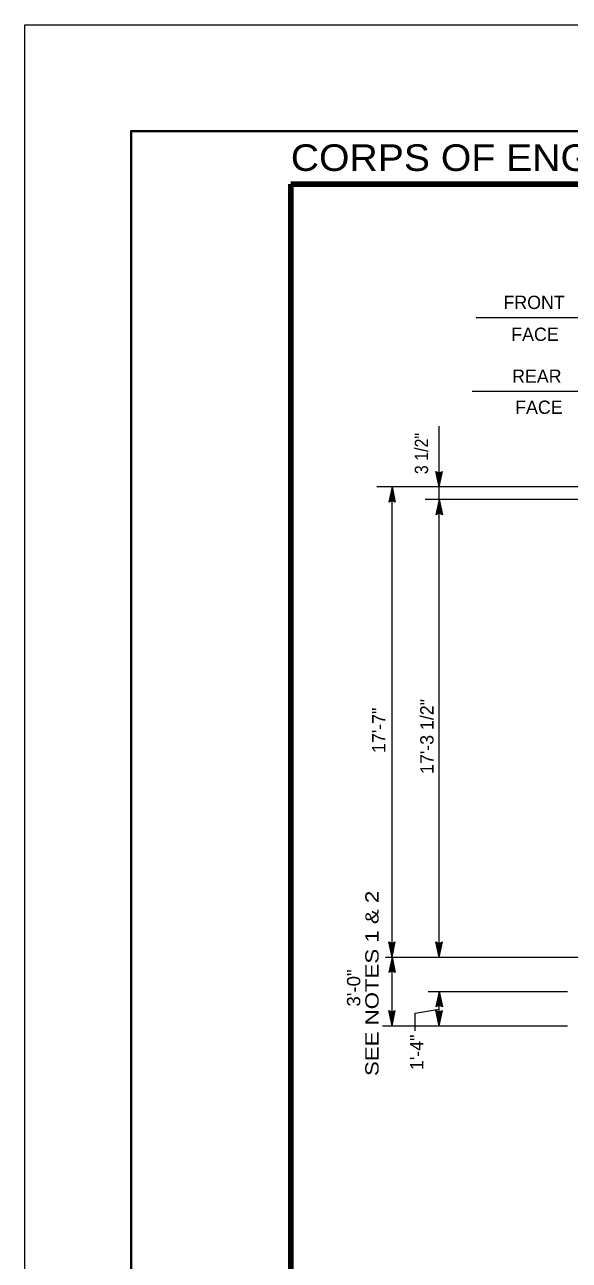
# Model space of a CAD drawing. Extents: x -22.3 to 19.7, y -11.8 to 18.2.
# Drawn here: x -22.31 to -17.19, y 6.54 to 18.16 of the extents above; entities that cross this region are included whole.
import ezdxf
from ezdxf.enums import TextEntityAlignment as Align

# ---------------------------------------------------------------- set-up
doc = ezdxf.new("R2010")
doc.units = 0
doc.header["$LTSCALE"] = 0.05
doc.layers.add('1', color=7, linetype='Continuous', lineweight=13)

msp = doc.modelspace()

# ---------------------------------------------------------------- linework, layer by layer
at = {"layer": '1'}
for p, q in [((-22.30942, -11.83969), (-22.30942, 18.16031)), ((-18.41442, 13.81631), (-18.44542, 13.96031)), ((-18.41442, 13.85331), (-18.43442, 13.94731)), ((-18.43442, 13.94731), (-18.41442, 13.93831)), ((-18.41442, 13.81631), (-18.38342, 13.96031)), ((-18.41442, 13.85331), (-18.39442, 13.94731)), ((-18.41442, 13.93831), (-18.39442, 13.94731)), ((-18.41442, 13.88931), (-18.42442, 13.93431)), ((-18.42442, 13.93431), (-18.41442, 13.93031)), ((-18.41442, 13.88931), (-18.40542, 13.93431)), ((-18.41442, 13.93031), (-18.40542, 13.93431)), ((-8.56742, 13.81631), (-19.00142, 13.81631)), ((-18.85842, 13.81631), (-18.88942, 13.67231)), ((-18.85842, 13.77931), (-18.87842, 13.68531)), ((-18.85842, 13.74331), (-18.86742, 13.69831)), ((-18.85842, 13.81631), (-18.82742, 13.67231)), ((-18.85842, 13.77931), (-18.83842, 13.68531)), ((-18.85842, 13.74331), (-18.84842, 13.69831)), ((-18.85842, 13.69431), (-18.87842, 13.68531)), ((-18.85842, 13.70231), (-18.86742, 13.69831)), ((-18.84842, 13.69831), (-18.85842, 13.70231)), ((-18.83842, 13.68531), (-18.85842, 13.69431)), ((-8.56742, 13.69631), (-18.54542, 13.69631)), ((-18.41442, 13.69631), (-18.44542, 13.55231)), ((-18.41442, 13.65931), (-18.43442, 13.56531)), ((-18.41442, 13.62331), (-18.42342, 13.57831)), ((-18.41442, 13.69631), (-18.38342, 13.55231)), ((-18.41442, 13.65931), (-18.39442, 13.56531)), ((-18.41442, 13.62331), (-18.40442, 13.57831)), ((-18.41442, 13.57431), (-18.43442, 13.56531)), ((-18.41442, 13.58231), (-18.42342, 13.57831)), ((-18.40442, 13.57831), (-18.41442, 13.58231)), ((-18.39442, 13.56531), (-18.41442, 13.57431)), ((-18.85842, 9.39231), (-18.88942, 9.53631)), ((-18.85842, 9.39231), (-18.82742, 9.53631)), ((-18.41442, 9.39231), (-18.44542, 9.53631)), ((-18.41442, 9.39231), (-18.38342, 9.53631)), ((-18.85842, 9.42931), (-18.87842, 9.52331)), ((-18.87842, 9.52331), (-18.85842, 9.51431)), ((-18.85842, 9.46531), (-18.86842, 9.51031)), ((-18.86842, 9.51031), (-18.85842, 9.50631)), ((-18.85842, 9.42931), (-18.83842, 9.52331)), ((-18.85842, 9.51431), (-18.83842, 9.52331)), ((-18.85842, 9.46531), (-18.84942, 9.51031)), ((-18.85842, 9.50631), (-18.84942, 9.51031)), ((-18.41442, 9.42931), (-18.43442, 9.52331)), ((-18.43442, 9.52331), (-18.41442, 9.51431)), ((-18.41442, 9.46531), (-18.42442, 9.51031)), ((-18.42442, 9.51031), (-18.41442, 9.50631)), ((-18.41442, 9.42931), (-18.39442, 9.52331)), ((-18.41442, 9.51431), (-18.39442, 9.52331)), ((-18.41442, 9.46531), (-18.40542, 9.51031)), ((-18.41442, 9.50631), (-18.40542, 9.51031)), ((-18.92042, 9.39231), (-15.40142, 9.39231)), ((-18.85842, 9.39231), (-18.88942, 9.24831)), ((-18.85842, 9.35531), (-18.87842, 9.26131)), ((-18.85842, 9.31931), (-18.86742, 9.27431)), ((-18.85842, 9.39231), (-18.82742, 9.24831)), ((-18.85842, 9.35531), (-18.83842, 9.26131)), ((-18.85842, 9.31931), (-18.84842, 9.27431)), ((-18.85842, 9.27031), (-18.87842, 9.26131)), ((-18.85842, 9.27831), (-18.86742, 9.27431)), ((-18.84842, 9.27431), (-18.85842, 9.27831)), ((-18.83842, 9.26131), (-18.85842, 9.27031)), ((-18.51842, 9.07131), (-17.21042, 9.07131)), ((-18.41442, 9.07131), (-18.44542, 8.92731)), ((-18.41442, 8.74831), (-18.41442, 9.07131)), ((-18.41442, 9.07131), (-18.38342, 8.92731)), ((-18.41442, 9.03431), (-18.43442, 8.94031)), ((-18.41442, 8.94931), (-18.43442, 8.94031)), ((-18.41442, 8.99831), (-18.42342, 8.95331)), ((-18.41442, 8.95731), (-18.42342, 8.95331)), ((-18.41442, 9.03431), (-18.39442, 8.94031)), ((-18.41442, 8.99831), (-18.40442, 8.95331)), ((-18.40442, 8.95331), (-18.41442, 8.95731)), ((-18.39442, 8.94031), (-18.41442, 8.94931)), ((-18.85842, 8.74831), (-18.88942, 8.89231)), ((-18.85842, 8.78531), (-18.87842, 8.87931)), ((-18.87842, 8.87931), (-18.85842, 8.87031)), ((-18.85842, 8.82131), (-18.86842, 8.86631)), ((-18.86842, 8.86631), (-18.85842, 8.86231)), ((-18.85842, 8.74831), (-18.82742, 8.89231)), ((-18.85842, 8.78531), (-18.83842, 8.87931)), ((-18.85842, 8.87031), (-18.83842, 8.87931)), ((-18.85842, 8.82131), (-18.84942, 8.86631)), ((-18.85842, 8.86231), (-18.84942, 8.86631)), ((-18.41442, 8.74831), (-18.44542, 8.89231)), ((-18.41442, 8.78531), (-18.43442, 8.87931)), ((-18.43442, 8.87931), (-18.41442, 8.87031)), ((-18.41442, 8.82131), (-18.42442, 8.86631)), ((-18.42442, 8.86631), (-18.41442, 8.86231)), ((-18.41442, 8.74831), (-18.38342, 8.89231)), ((-18.41442, 8.78531), (-18.39442, 8.87931)), ((-18.41442, 8.87031), (-18.39442, 8.87931)), ((-18.41442, 8.82131), (-18.40542, 8.86631)), ((-18.41442, 8.86231), (-18.40542, 8.86631)), ((-18.94642, 8.74831), (-17.21042, 8.74831))]:
    msp.add_line(p, q, dxfattribs=at)
for points in [[(-22.30942, 18.16031), (19.69058, 18.16031), (19.69058, -11.83969)], [(-18.06742, 15.40731), (-17.03142, 15.40731), (-16.93242, 15.40731), (-10.43842, 15.40731), (-10.30242, 15.40731), (-8.44242, 15.40731), (-8.32942, 15.40731), (-7.44542, 15.40731)], [(-18.10442, 14.71431), (-17.03142, 14.71431), (-16.93242, 14.71431), (-14.20242, 14.71431), (-13.95142, 14.71431), (-12.68842, 14.71431), (-12.43842, 14.71431), (-11.43942, 14.71431), (-11.31142, 14.71431), (-10.43842, 14.71431), (-10.30342, 14.71431), (-9.17242, 14.71431), (-9.07942, 14.71431), (-8.44242, 14.71431), (-8.33342, 14.71431), (-7.78542, 14.71431)], [(-18.41442, 9.39231), (-18.41442, 13.69631), (-18.41442, 13.81631), (-18.41442, 14.38631)], [(-18.44542, 13.96031), (-18.41442, 13.94631), (-18.38342, 13.96031)], [(-18.85842, 8.74831), (-18.85842, 9.39231), (-18.85842, 13.81631)], [(-18.82742, 13.67231), (-18.85842, 13.68631), (-18.88942, 13.67231)], [(-18.38342, 13.55231), (-18.41442, 13.56631), (-18.44542, 13.55231)], [(-18.88942, 9.53631), (-18.85842, 9.52231), (-18.82742, 9.53631)], [(-18.44542, 9.53631), (-18.41442, 9.52231), (-18.38342, 9.53631)], [(-18.82742, 9.24831), (-18.85842, 9.26231), (-18.88942, 9.24831)], [(-18.88942, 8.89231), (-18.85842, 8.87831), (-18.82742, 8.89231)], [(-18.64042, 8.70131), (-18.64042, 8.86731), (-18.41442, 8.90531)], [(-18.38342, 8.92731), (-18.41442, 8.94131), (-18.44542, 8.92731)], [(-18.44542, 8.89231), (-18.41442, 8.87831), (-18.38342, 8.89231)]]:
    msp.add_lwpolyline(points, dxfattribs=at)
at = {"layer": '1', "lineweight": 40}
msp.add_lwpolyline([(-21.30942, -10.83969), (-21.30942, 17.16031), (18.69058, 17.16031), (18.69058, -10.83969)], close=True, dxfattribs=at)
at = {"layer": '1', "lineweight": 90}
msp.add_lwpolyline([(-19.80942, 16.66031), (18.19058, 16.66031), (18.19058, -10.33969), (-19.80942, -10.33969)], close=True, dxfattribs=at)

# ---------------------------------------------------------------- texts
at = {"layer": '1', "width": 1.1}
msp.add_text('CORPS OF ENGINEERS', height=0.25, dxfattribs=at).set_placement((-19.80942, 16.78531))
at = {"layer": '1'}
for s, p in [('FRONT', (-17.23542, 15.48731)), ('FACE', (-17.29242, 15.18731)), ('REAR', (-17.26542, 14.79331)), ('FACE', (-17.25542, 14.50131))]:
    msp.add_text(s, height=0.125, dxfattribs=at).set_placement(p, align=Align.RIGHT)
at = {"layer": '1', "width": 0.9}
msp.add_text('3 1/2"', height=0.125, rotation=90, dxfattribs=at).set_placement((-18.51942, 13.93431))
at = {"layer": '1'}
for s, p in [('17\'-3 1/2"', (-18.46842, 11.46831)), ('17\'-7"', (-18.92042, 11.52631)), ('1\'-4"', (-18.56342, 8.49881))]:
    msp.add_text(s, height=0.125, rotation=90, dxfattribs=at).set_placement(p, align=Align.CENTER)
for s, width, p in [('SEE NOTES 1 & 2', 1.25, (-18.98442, 9.14681)), ('3\'-0"', 1.05, (-19.15642, 9.10331))]:
    msp.add_text(s, height=0.125, rotation=90, dxfattribs=dict(at, width=width)).set_placement(p, align=Align.CENTER)

doc.saveas('drawing.dxf')
